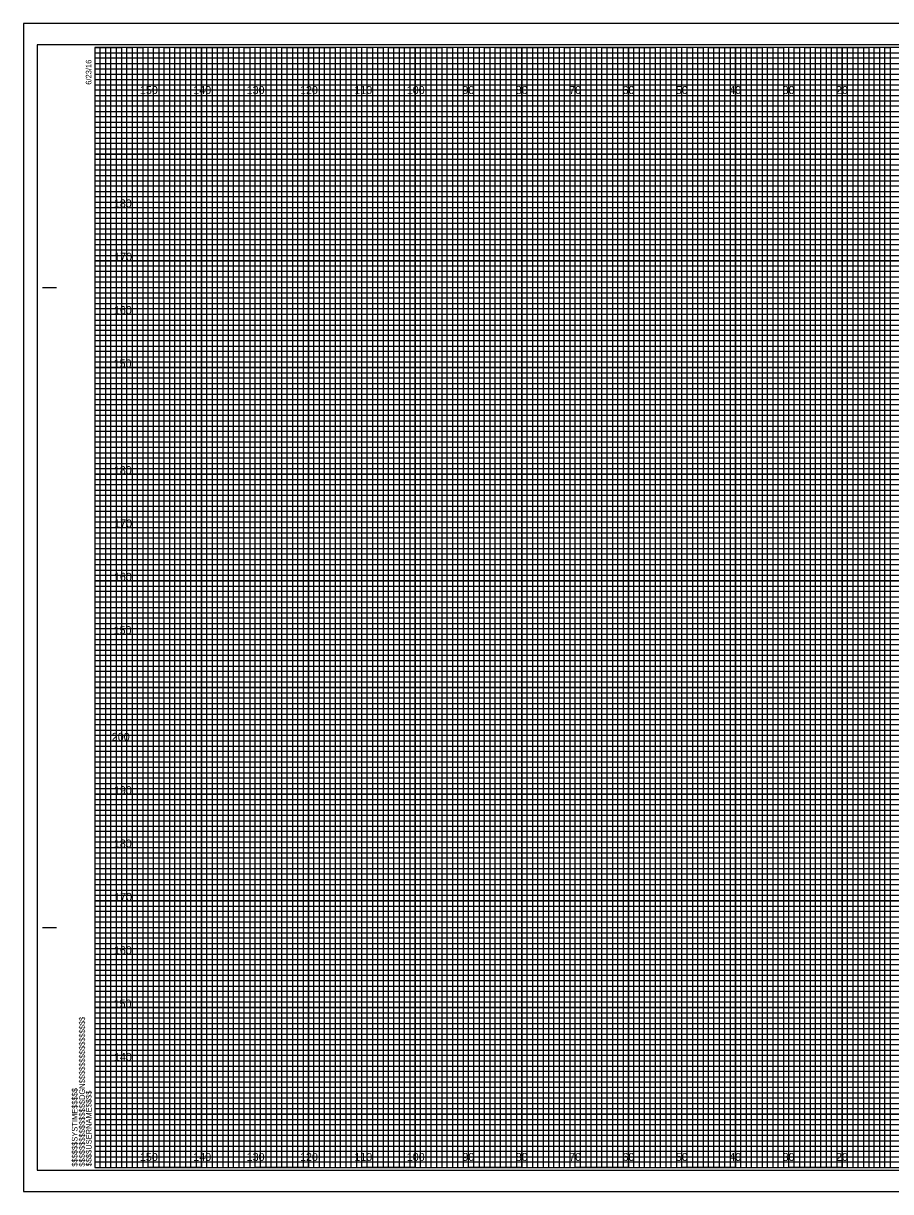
# Model space of a CAD drawing. Extents: x -13 to 323, y -5 to 654.
# Drawn here: x -13.4 to 149.1, y 215.5 to 434.5 of the extents above; entities that cross this region are included whole.
import ezdxf

# ---------------------------------------------------------------- set-up
doc = ezdxf.new("R2010")
doc.units = 0
for name, color, linetype in [('Exist Cross Section Cell', 7, 'Continuous'), ('Exist XS Center Line Elevation Label', 7, 'Continuous'), ('Exist XS Ground Line', 7, 'Continuous'), ('Prop CMT Guardrail Graphics', 7, 'Continuous'), ('Prop CMT Pvmt Course 1', 7, 'Continuous'), ('Prop CMT Pvmt Course 2', 7, 'Continuous'), ('Prop CMT Pvmt Course 3', 7, 'Continuous'), ('Prop CMT Shld Paved Course 1', 7, 'Continuous'), ('Prop CMT Shld Paved Course 2', 7, 'Continuous'), ('Prop CMT Subgrade Earthwork', 7, 'Continuous'), ('Scratch_Level_0', 7, 'Continuous')]:
    doc.layers.add(name, color=color, linetype=linetype)

msp = doc.modelspace()

# ---------------------------------------------------------------- linework, layer by layer
at = {"layer": 'Exist XS Center Line Elevation Label'}
for points in [[(0, 430), (5, 430), (5, 220), (15, 220), (15, 430), (25, 430), (25, 220), (35, 220), (35, 430), (45, 430), (45, 220), (55, 220), (55, 430), (65, 430), (65, 220), (75, 220), (75, 430), (85, 430), (85, 220), (95, 220), (95, 430), (105, 430), (105, 220), (115, 220), (115, 430), (125, 430), (125, 220), (135, 220), (135, 430), (145, 430), (145, 220), (155, 220)], [(0, 425), (275, 425)], [(0, 405), (320, 405), (320, 415), (0, 415)], [(0, 385), (320, 385), (320, 395), (0, 395)], [(0, 365), (320, 365), (320, 375), (0, 375)], [(0, 345), (320, 345), (320, 355), (0, 355)], [(0, 325), (320, 325), (320, 335), (0, 335)], [(0, 305), (320, 305), (320, 315), (0, 315)], [(0, 285), (320, 285), (320, 295), (0, 295)], [(0, 265), (320, 265), (320, 275), (0, 275)], [(0, 245), (320, 245), (320, 255), (0, 255)], [(0, 225), (320, 225), (320, 235), (0, 235)]]:
    msp.add_lwpolyline(points, dxfattribs=at)
at = {"layer": 'Exist XS Ground Line'}
for p, q in [((10, 430), (0, 430)), ((10, 220), (10, 430)), ((30, 430), (20, 430)), ((20, 430), (20, 220)), ((30, 220), (30, 430)), ((50, 430), (40, 430)), ((40, 430), (40, 220)), ((50, 220), (50, 430)), ((70, 430), (60, 430)), ((60, 430), (60, 220)), ((70, 220), (70, 430)), ((90, 430), (80, 430)), ((80, 430), (80, 220)), ((90, 220), (90, 430)), ((110, 430), (100, 430)), ((100, 430), (100, 220)), ((110, 220), (110, 430)), ((130, 430), (120, 430)), ((120, 430), (120, 220)), ((130, 220), (130, 430)), ((150, 430), (140, 430)), ((140, 430), (140, 220)), ((20, 220), (10, 220)), ((40, 220), (30, 220)), ((60, 220), (50, 220)), ((80, 220), (70, 220)), ((100, 220), (90, 220)), ((120, 220), (110, 220)), ((140, 220), (130, 220))]:
    msp.add_line(p, q, dxfattribs=at)
for points in [[(0, 420), (320, 420), (320, 410), (0, 410)], [(0, 400), (320, 400), (320, 390), (0, 390)], [(0, 380), (320, 380), (320, 370), (0, 370)], [(0, 360), (320, 360), (320, 350), (0, 350)], [(0, 340), (320, 340), (320, 330), (0, 330)], [(0, 320), (320, 320), (320, 310), (0, 310)], [(0, 300), (320, 300), (320, 290), (0, 290)], [(0, 280), (320, 280), (320, 270), (0, 270)], [(0, 260), (320, 260), (320, 250), (0, 250)], [(0, 240), (320, 240), (320, 230), (0, 230)]]:
    msp.add_lwpolyline(points, dxfattribs=at)
at = {"layer": 'Prop CMT Pvmt Course 1'}
for p, q in [((323.3, 434.5), (-13.4, 434.5)), ((-13.4, 434.5), (-13.4, 215.5)), ((-13.4, 215.5), (323.3, 215.5))]:
    msp.add_line(p, q, dxfattribs=at)
at = {"layer": 'Prop CMT Pvmt Course 2'}
msp.add_lwpolyline([(-13.4, 215.5), (323.3, 215.5), (323.3, 434.5), (-13.4, 434.5)], close=True, dxfattribs=at)
at = {"layer": 'Prop CMT Pvmt Course 3'}
msp.add_lwpolyline([(-10.8, 219.5), (322.4, 219.5), (322.4, 430.5), (-10.8, 430.5)], close=True, dxfattribs=at)
at = {"layer": 'Prop CMT Shld Paved Course 1'}
for p, q in [((-9.8, 385), (-7.3, 385)), ((-9.7, 385), (-7.2, 385)), ((-9.8, 265), (-7.3, 265)), ((-9.7, 265), (-7.2, 265)), ((0, 220), (0, 220)), ((0, 220), (0, 220)), ((0, 220), (0, 220)), ((0, 220), (0, 220)), ((0, 220), (0, 220)), ((0, 220), (0, 220)), ((0, 220), (0, 220))]:
    msp.add_line(p, q, dxfattribs=at)
msp.add_lwpolyline([(320, 430), (0, 430), (0, 220), (320, 220)], close=True, dxfattribs=at)
at = {"layer": 'Prop CMT Shld Paved Course 2'}
for points in [[(0, 220), (1, 220), (1, 430), (2, 430), (2, 220)], [(2, 220), (3, 220), (3, 430), (4, 430), (4, 220)], [(5, 220), (6, 220), (6, 430), (7, 430), (7, 220)], [(7, 220), (8, 220), (8, 430), (9, 430), (9, 220)], [(10, 220), (11, 220), (11, 430), (12, 430), (12, 220)], [(12, 220), (13, 220), (13, 430), (14, 430), (14, 220)], [(15, 220), (16, 220), (16, 430), (17, 430), (17, 220)], [(17, 220), (18, 220), (18, 430), (19, 430), (19, 220)], [(20, 220), (21, 220), (21, 430), (22, 430), (22, 220)], [(22, 220), (23, 220), (23, 430), (24, 430), (24, 220)], [(25, 220), (26, 220), (26, 430), (27, 430), (27, 220)], [(27, 220), (28, 220), (28, 430), (29, 430), (29, 220)], [(30, 220), (31, 220), (31, 430), (32, 430), (32, 220)], [(32, 220), (33, 220), (33, 430), (34, 430), (34, 220)], [(35, 220), (36, 220), (36, 430), (37, 430), (37, 220)], [(37, 220), (38, 220), (38, 430), (39, 430), (39, 220)], [(40, 220), (41, 220), (41, 430), (42, 430), (42, 220)], [(42, 220), (43, 220), (43, 430), (44, 430), (44, 220)], [(45, 220), (46, 220), (46, 430), (47, 430), (47, 220)], [(47, 220), (48, 220), (48, 430), (49, 430), (49, 220)], [(50, 220), (51, 220), (51, 430), (52, 430), (52, 220)], [(52, 220), (53, 220), (53, 430), (54, 430), (54, 220)], [(55, 220), (56, 220), (56, 430), (57, 430), (57, 220)], [(57, 220), (58, 220), (58, 430), (59, 430), (59, 220)], [(60, 220), (61, 220), (61, 430), (62, 430), (62, 220)], [(62, 220), (63, 220), (63, 430), (64, 430), (64, 220)], [(65, 220), (66, 220), (66, 430), (67, 430), (67, 220)], [(67, 220), (68, 220), (68, 430), (69, 430), (69, 220)], [(70, 220), (71, 220), (71, 430), (72, 430), (72, 220)], [(72, 220), (73, 220), (73, 430), (74, 430), (74, 220)], [(75, 220), (76, 220), (76, 430), (77, 430), (77, 220)], [(77, 220), (78, 220), (78, 430), (79, 430), (79, 220)], [(80, 220), (81, 220), (81, 430), (82, 430), (82, 220)], [(82, 220), (83, 220), (83, 430), (84, 430), (84, 220)], [(85, 220), (86, 220), (86, 430), (87, 430), (87, 220)], [(87, 220), (88, 220), (88, 430), (89, 430), (89, 220)], [(90, 220), (91, 220), (91, 430), (92, 430), (92, 220)], [(92, 220), (93, 220), (93, 430), (94, 430), (94, 220)], [(95, 220), (96, 220), (96, 430), (97, 430), (97, 220)], [(97, 220), (98, 220), (98, 430), (99, 430), (99, 220)], [(100, 220), (101, 220), (101, 430), (102, 430), (102, 220)], [(102, 220), (103, 220), (103, 430), (104, 430), (104, 220)], [(105, 220), (106, 220), (106, 430), (107, 430), (107, 220)], [(107, 220), (108, 220), (108, 430), (109, 430), (109, 220)], [(110, 220), (111, 220), (111, 430), (112, 430), (112, 220)], [(112, 220), (113, 220), (113, 430), (114, 430), (114, 220)], [(115, 220), (116, 220), (116, 430), (117, 430), (117, 220)], [(117, 220), (118, 220), (118, 430), (119, 430), (119, 220)], [(120, 220), (121, 220), (121, 430), (122, 430), (122, 220)], [(122, 220), (123, 220), (123, 430), (124, 430), (124, 220)], [(125, 220), (126, 220), (126, 430), (127, 430), (127, 220)], [(127, 220), (128, 220), (128, 430), (129, 430), (129, 220)], [(130, 220), (131, 220), (131, 430), (132, 430), (132, 220)], [(132, 220), (133, 220), (133, 430), (134, 430), (134, 220)], [(135, 220), (136, 220), (136, 430), (137, 430), (137, 220)], [(137, 220), (138, 220), (138, 430), (139, 430), (139, 220)], [(140, 220), (141, 220), (141, 430), (142, 430), (142, 220)], [(142, 220), (143, 220), (143, 430), (144, 430), (144, 220)], [(145, 220), (146, 220), (146, 430), (147, 430), (147, 220)], [(147, 220), (148, 220), (148, 430), (149, 430), (149, 220)]]:
    msp.add_lwpolyline(points, dxfattribs=at)
at = {"layer": 'Prop CMT Subgrade Earthwork'}
for p, q in [((10, 220), (10, 430)), ((20, 220), (20, 430)), ((30, 220), (30, 430)), ((40, 220), (40, 430)), ((50, 220), (50, 430)), ((60, 220), (60, 430)), ((70, 220), (70, 430)), ((80, 220), (80, 430)), ((90, 220), (90, 430)), ((100, 220), (100, 430)), ((110, 220), (110, 430)), ((120, 220), (120, 430)), ((130, 220), (130, 430)), ((140, 220), (140, 430)), ((0, 420), (320, 420)), ((0, 410), (320, 410)), ((0, 400), (320, 400)), ((0, 390), (320, 390)), ((0, 380), (320, 380)), ((0, 370), (320, 370)), ((0, 360), (320, 360)), ((0, 350), (320, 350)), ((0, 340), (320, 340)), ((0, 330), (320, 330)), ((0, 320), (320, 320)), ((0, 310), (320, 310)), ((0, 300), (320, 300)), ((0, 290), (320, 290)), ((0, 280), (320, 280)), ((0, 270), (320, 270)), ((0, 260), (320, 260)), ((0, 250), (320, 250)), ((0, 240), (320, 240)), ((0, 230), (320, 230))]:
    msp.add_line(p, q, dxfattribs=at)
at = {"layer": 'Scratch_Level_0'}
for p, q in [((0, 429), (260, 429)), ((260, 427.98), (0, 427.98)), ((0, 427.98), (0, 427)), ((0, 427), (260, 427)), ((260, 425.89), (0, 425.89)), ((0, 425.89), (0, 424)), ((0, 424), (320, 424))]:
    msp.add_line(p, q, dxfattribs=at)
for points in [[(0, 423), (270, 423), (320, 423), (320, 422), (0, 422)], [(0, 421), (320, 421), (320, 419), (0, 419)], [(0, 418), (320, 418), (320, 417), (0, 416.98)], [(0, 416), (320, 416), (320, 414), (0, 414)], [(0, 413), (320, 413), (320, 412), (0, 412)], [(0, 411), (320, 411), (320, 409), (0, 409)], [(0, 408), (320, 408), (320, 407), (0, 407)], [(0, 406), (320, 406), (320, 404), (0, 404)], [(0, 403), (320, 403), (320, 402), (0, 402)], [(0, 401), (320, 401), (320, 399), (0, 399)], [(0, 398), (320, 398), (320, 397), (0, 397)], [(0, 396), (320, 396), (320, 393.95), (320, 393), (320, 392), (0, 392)], [(0, 394), (320, 394), (320, 393), (0, 393)], [(0, 391), (320, 391), (320, 389), (0, 389.03)], [(0, 389.03), (320, 389), (320, 388), (0, 388)], [(0, 387), (320, 387), (320, 386), (0, 386)], [(0, 384), (320, 384), (320, 383), (0, 383)], [(0, 382), (320, 382), (320, 381), (0, 381)], [(-0.07, 378.89), (320, 378.89), (320, 377.88), (-0.07, 377.88)], [(0, 377), (320, 377), (320, 376), (0, 376)], [(0, 374), (320, 374), (320, 373), (0, 373)], [(0, 372), (320, 372), (320, 371), (0, 371)], [(0, 369), (320, 369), (320, 368), (0, 368)], [(0, 367), (320, 367), (320, 366), (0, 366)], [(0, 364), (320, 364), (320, 363), (0, 363)], [(0, 362), (320, 362), (320, 361), (0, 361)], [(0, 359), (320, 359), (319.99, 357.98), (0, 358)], [(0, 357), (320, 357), (320, 356), (0, 356)], [(0, 354), (320, 354), (320, 353), (0, 353)], [(0, 352), (320, 352), (320, 351), (0, 351)], [(0, 349), (320, 349), (320, 348), (0, 348)], [(0, 347), (320, 347), (320, 346), (0, 346)], [(0, 344), (320, 344), (320, 343), (0, 343)], [(0, 342), (320, 342), (320, 341), (0, 341)], [(0, 339), (320, 339), (320, 338), (0, 338)], [(0, 336.99), (320.07, 336.91), (320, 336), (0, 336)], [(0, 334), (320, 334), (320, 333), (0, 333)], [(0, 332), (320, 332), (320, 331), (0, 331)], [(0, 329), (320, 329), (320, 328), (0, 328)], [(0, 327), (320, 327), (320, 326), (0, 326)], [(0, 324), (320, 324), (320, 323), (0, 323)], [(0, 322), (320, 322), (320, 321), (0, 321)], [(0, 319), (320, 319), (320, 318), (0, 318)], [(0, 317), (320, 317), (320, 316), (0, 316)], [(0, 314), (320, 314), (320, 313), (0, 313)], [(0, 312), (320, 312), (320, 311), (0, 311)], [(0, 309), (320, 309), (320, 308), (0, 308)], [(0, 307), (320, 307), (320, 306), (0, 306)], [(0, 304), (320, 304), (320, 303), (0, 303)], [(0, 302), (320, 302), (320, 301), (0, 301)], [(0, 299), (320, 299), (319.99, 297.98), (0, 298)], [(0, 297), (320, 297), (320, 296), (0, 296)], [(0, 294), (320, 294), (320, 293), (0, 293)], [(0, 292), (320, 292), (320, 291), (0, 291)], [(0, 289), (320, 289), (320, 288), (0, 288)], [(0, 287), (320, 287), (320, 286), (0, 286)], [(0, 284), (320, 284), (320, 283), (0, 283)], [(0, 282), (320, 282), (320, 281), (0, 281)], [(0, 279), (320, 279), (320, 278), (0, 278)], [(0, 276.99), (320.07, 276.91), (320, 276), (0, 276)], [(0, 274), (320, 274), (320, 273), (0, 273)], [(0, 272), (320, 272), (320, 271), (0, 271)], [(0, 269), (320, 269), (320, 268), (0, 268)], [(0, 267), (320, 267), (320, 266), (0, 266)], [(0, 264), (320, 264), (320, 263), (0, 263)], [(0, 262), (320, 262), (320, 261), (0, 261)], [(0, 259), (320, 259), (320, 258), (0, 258)], [(0, 257), (320, 257), (320, 256), (0, 256)], [(0, 254), (320, 254), (320, 253), (0, 253)], [(0, 252), (320, 252), (320, 251), (0, 251)], [(0, 249), (320, 249), (320, 248), (0, 248)], [(0, 247), (320, 247), (320, 246), (0, 246)], [(0, 244), (320, 244), (320, 243), (0, 243)], [(0, 242), (320, 242), (320, 241), (0, 241)], [(0, 239), (320, 239), (320, 238), (0, 238)], [(0, 237), (320, 237), (320, 236), (0, 236)], [(0, 234), (320, 234), (320, 233), (0, 233)], [(0, 232), (320, 232), (320, 231), (0, 231)], [(0, 229), (320, 229), (320, 228), (0, 228)], [(0, 227), (320, 227), (320, 226), (0, 226)], [(0, 224), (320, 224), (320, 223), (0, 223)], [(0, 222), (320, 222), (320, 221), (0, 221)]]:
    msp.add_lwpolyline(points, dxfattribs=at)

# ---------------------------------------------------------------- texts
at = {"layer": 'Exist Cross Section Cell'}
for s, p in [('150', (8.44, 421.25)), ('140', (18.44, 421.25)), ('130', (28.44, 421.25)), ('120', (38.44, 421.25)), ('110', (48.62, 421.25)), ('100', (58.44, 421.25)), ('90', (68.86, 421.25)), ('80', (78.86, 421.25)), ('70', (88.86, 421.25)), ('60', (98.86, 421.25)), ('50', (108.86, 421.25)), ('40', (118.86, 421.25)), ('30', (128.86, 421.25)), ('20', (138.86, 421.25)), ('150', (8.44, 221.25)), ('140', (18.44, 221.25)), ('130', (28.44, 221.25)), ('120', (38.44, 221.25)), ('110', (48.62, 221.25)), ('100', (58.44, 221.25)), ('90', (68.86, 221.25)), ('80', (78.86, 221.25)), ('70', (88.86, 221.25)), ('60', (98.86, 221.25)), ('50', (108.86, 221.25)), ('40', (118.86, 221.25)), ('30', (128.86, 221.25)), ('20', (138.86, 221.25))]:
    msp.add_text(s, height=1.5, dxfattribs=at).set_placement(p)
at = {"layer": 'Prop CMT Guardrail Graphics'}
for s, p in [('180', (3.55, 400)), ('170', (3.61, 390)), ('160', (3.57, 380)), ('150', (3.52, 370)), ('180', (3.55, 350)), ('170', (3.61, 340)), ('160', (3.57, 330)), ('150', (3.52, 320)), ('200', (3.17, 300)), ('190', (3.57, 290)), ('180', (3.55, 280)), ('170', (3.61, 270)), ('160', (3.57, 260)), ('150', (3.52, 250)), ('140', (3.57, 240))]:
    msp.add_text(s, height=1.5, dxfattribs=at).set_placement(p)
at = {"layer": 'Prop CMT Shld Paved Course 1'}
for s, p in [('6/23/16', (-0.65, 423)), ('$$$$$$$$$$$$$$$$DGN$$$$$$$$$$$$$$$$', (-1.88, 220.18)), ('$$$$$$SYSTIME$$$$$', (-3.26, 220.18)), ('$$$$USERNAME$$$$', (-0.62, 220.23))]:
    msp.add_text(s, height=1.05, rotation=90, dxfattribs=at).set_placement(p)

doc.saveas('drawing.dxf')
